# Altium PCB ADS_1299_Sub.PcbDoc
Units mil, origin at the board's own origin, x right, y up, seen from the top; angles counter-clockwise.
Board outline 2450.29 x 2305.45 mil, 4 copper layers (Top Layer, GND, DVDD, Bottom Layer), stack 23.756 mil thick; 58 components, 57 nets, 236 pads, 60 vias.
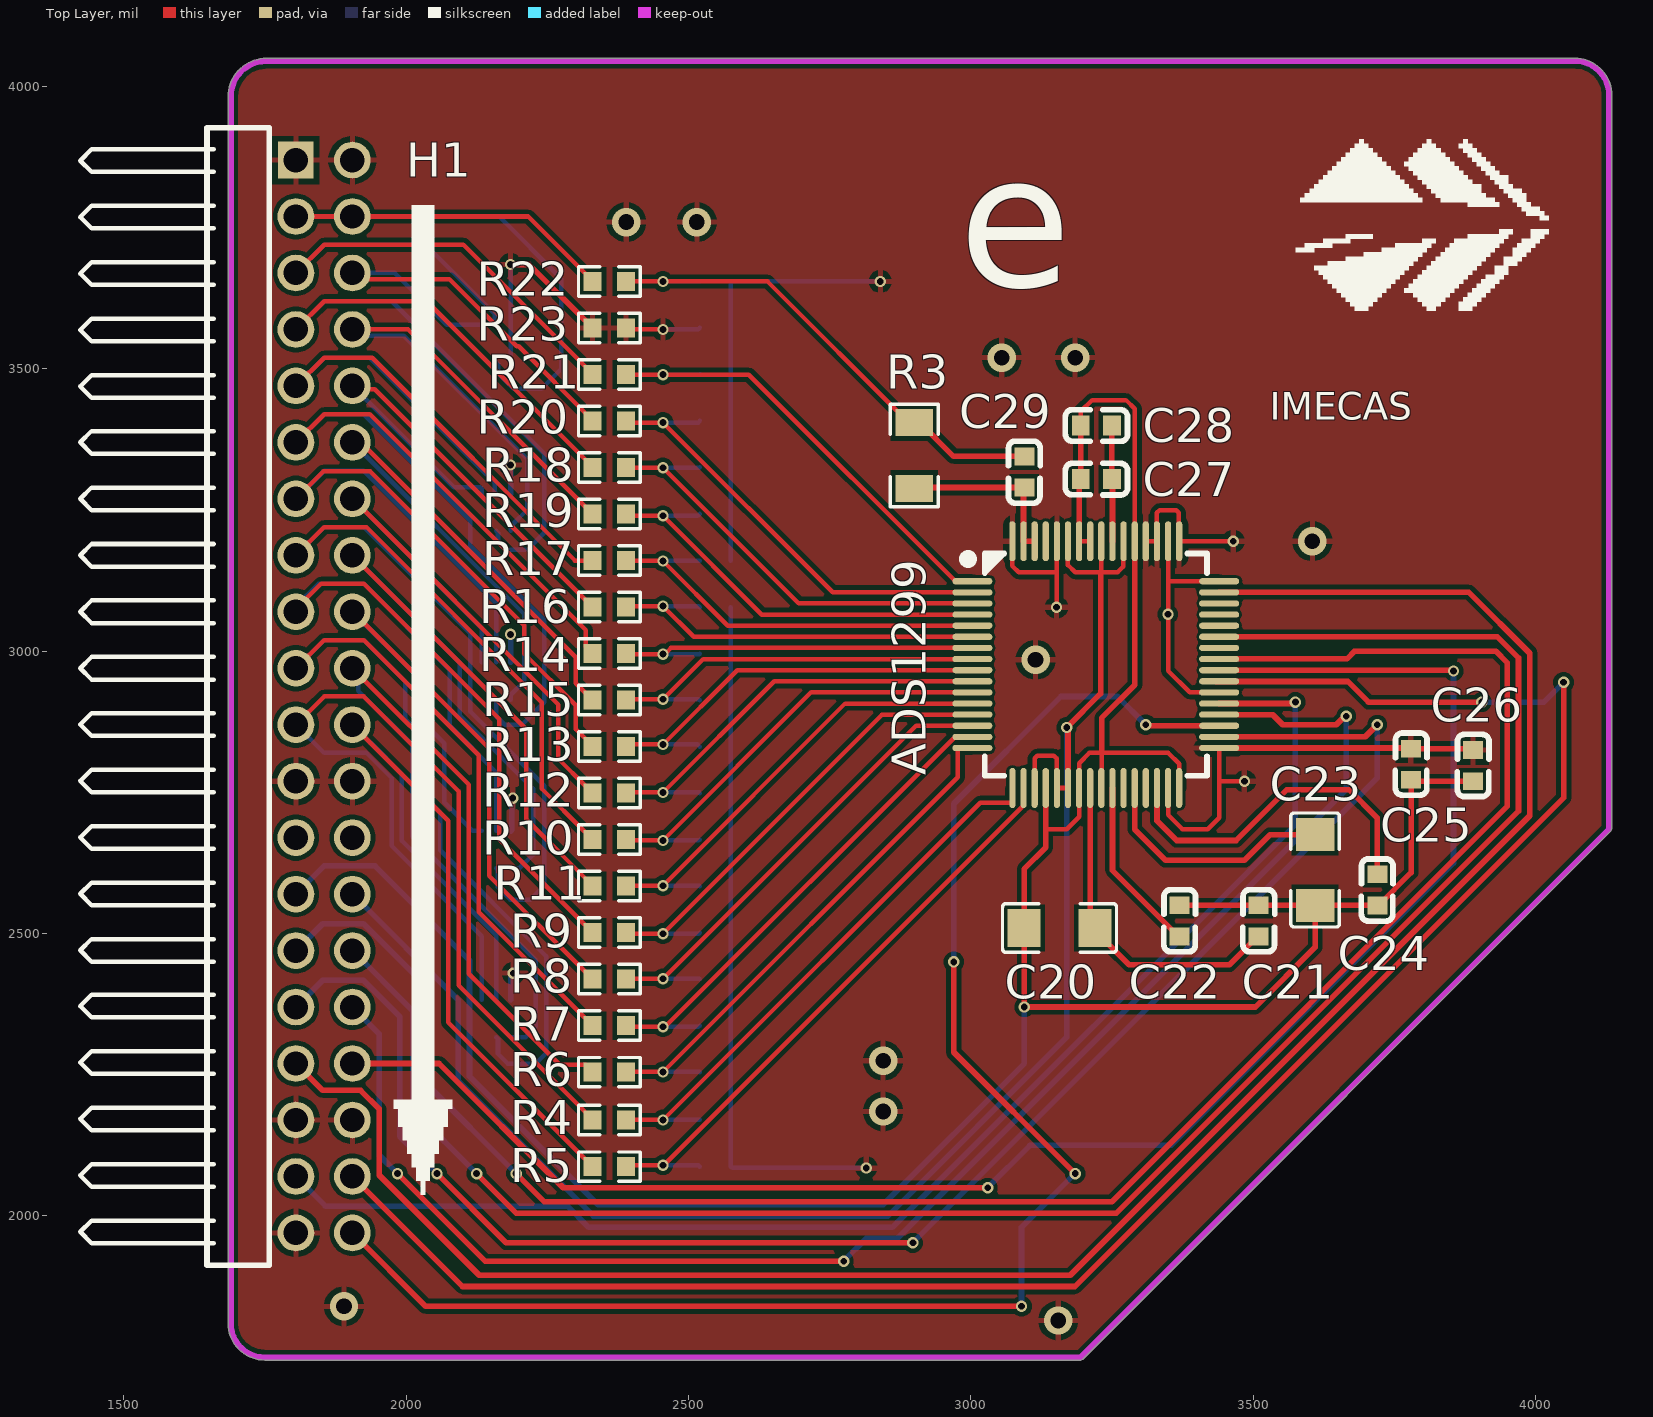
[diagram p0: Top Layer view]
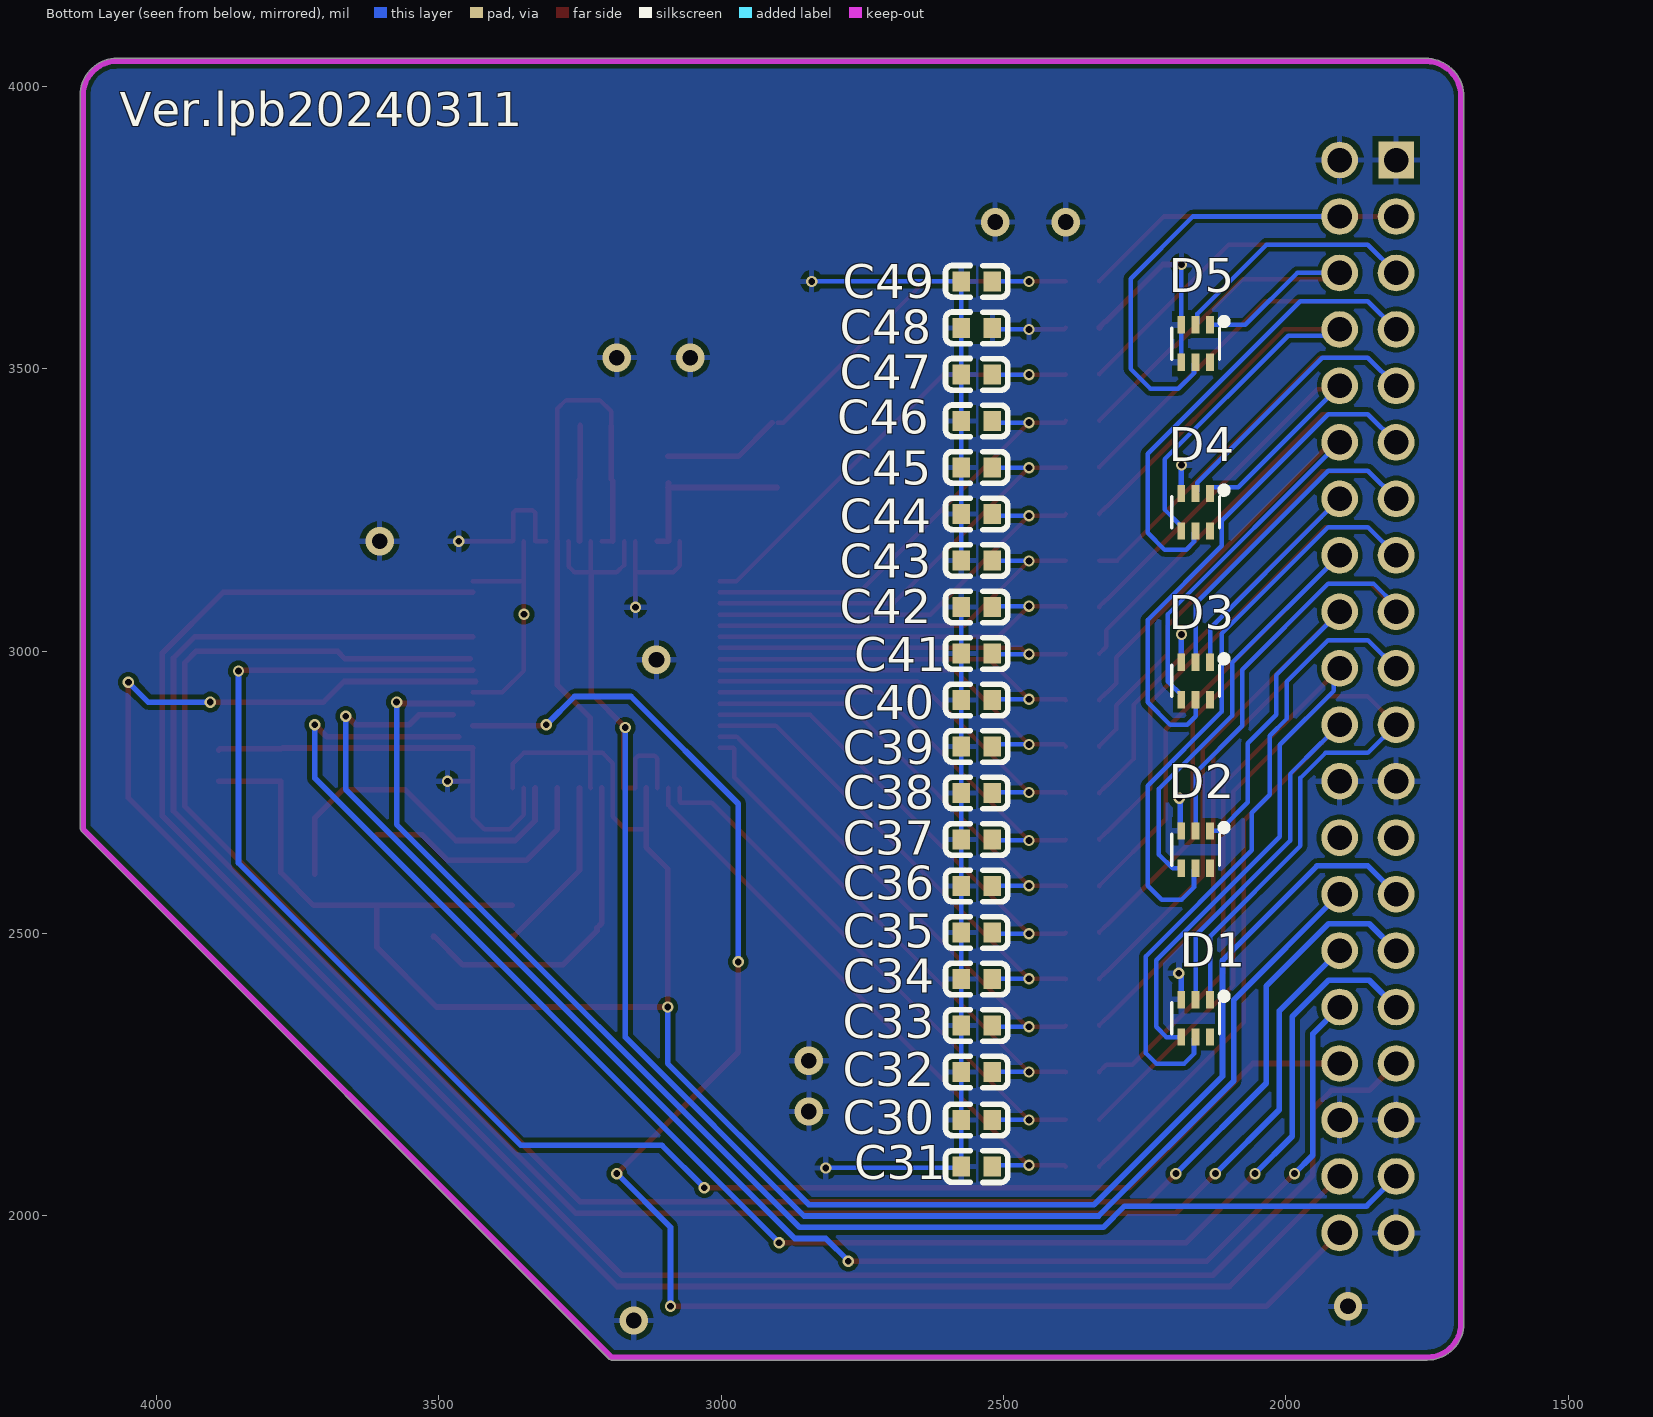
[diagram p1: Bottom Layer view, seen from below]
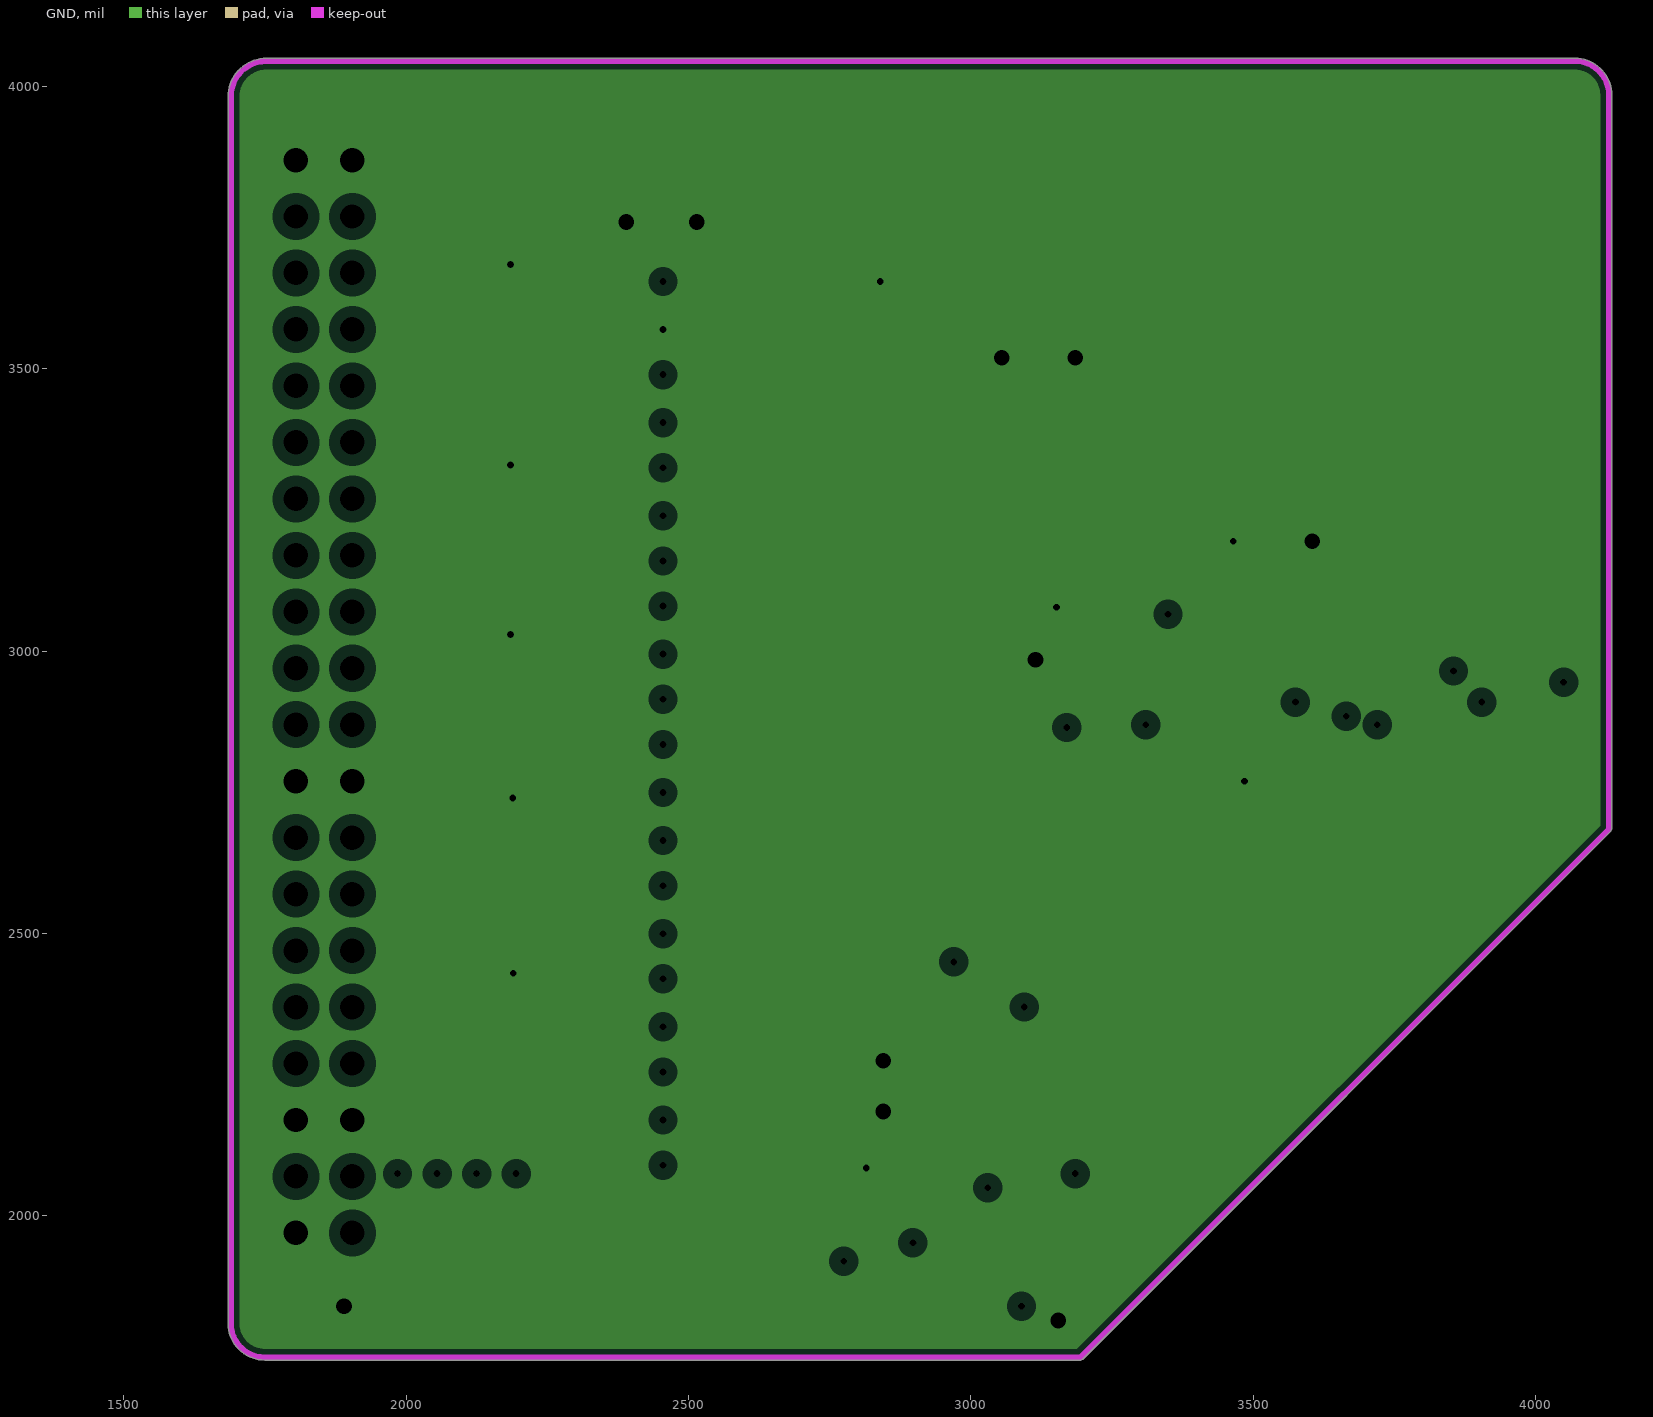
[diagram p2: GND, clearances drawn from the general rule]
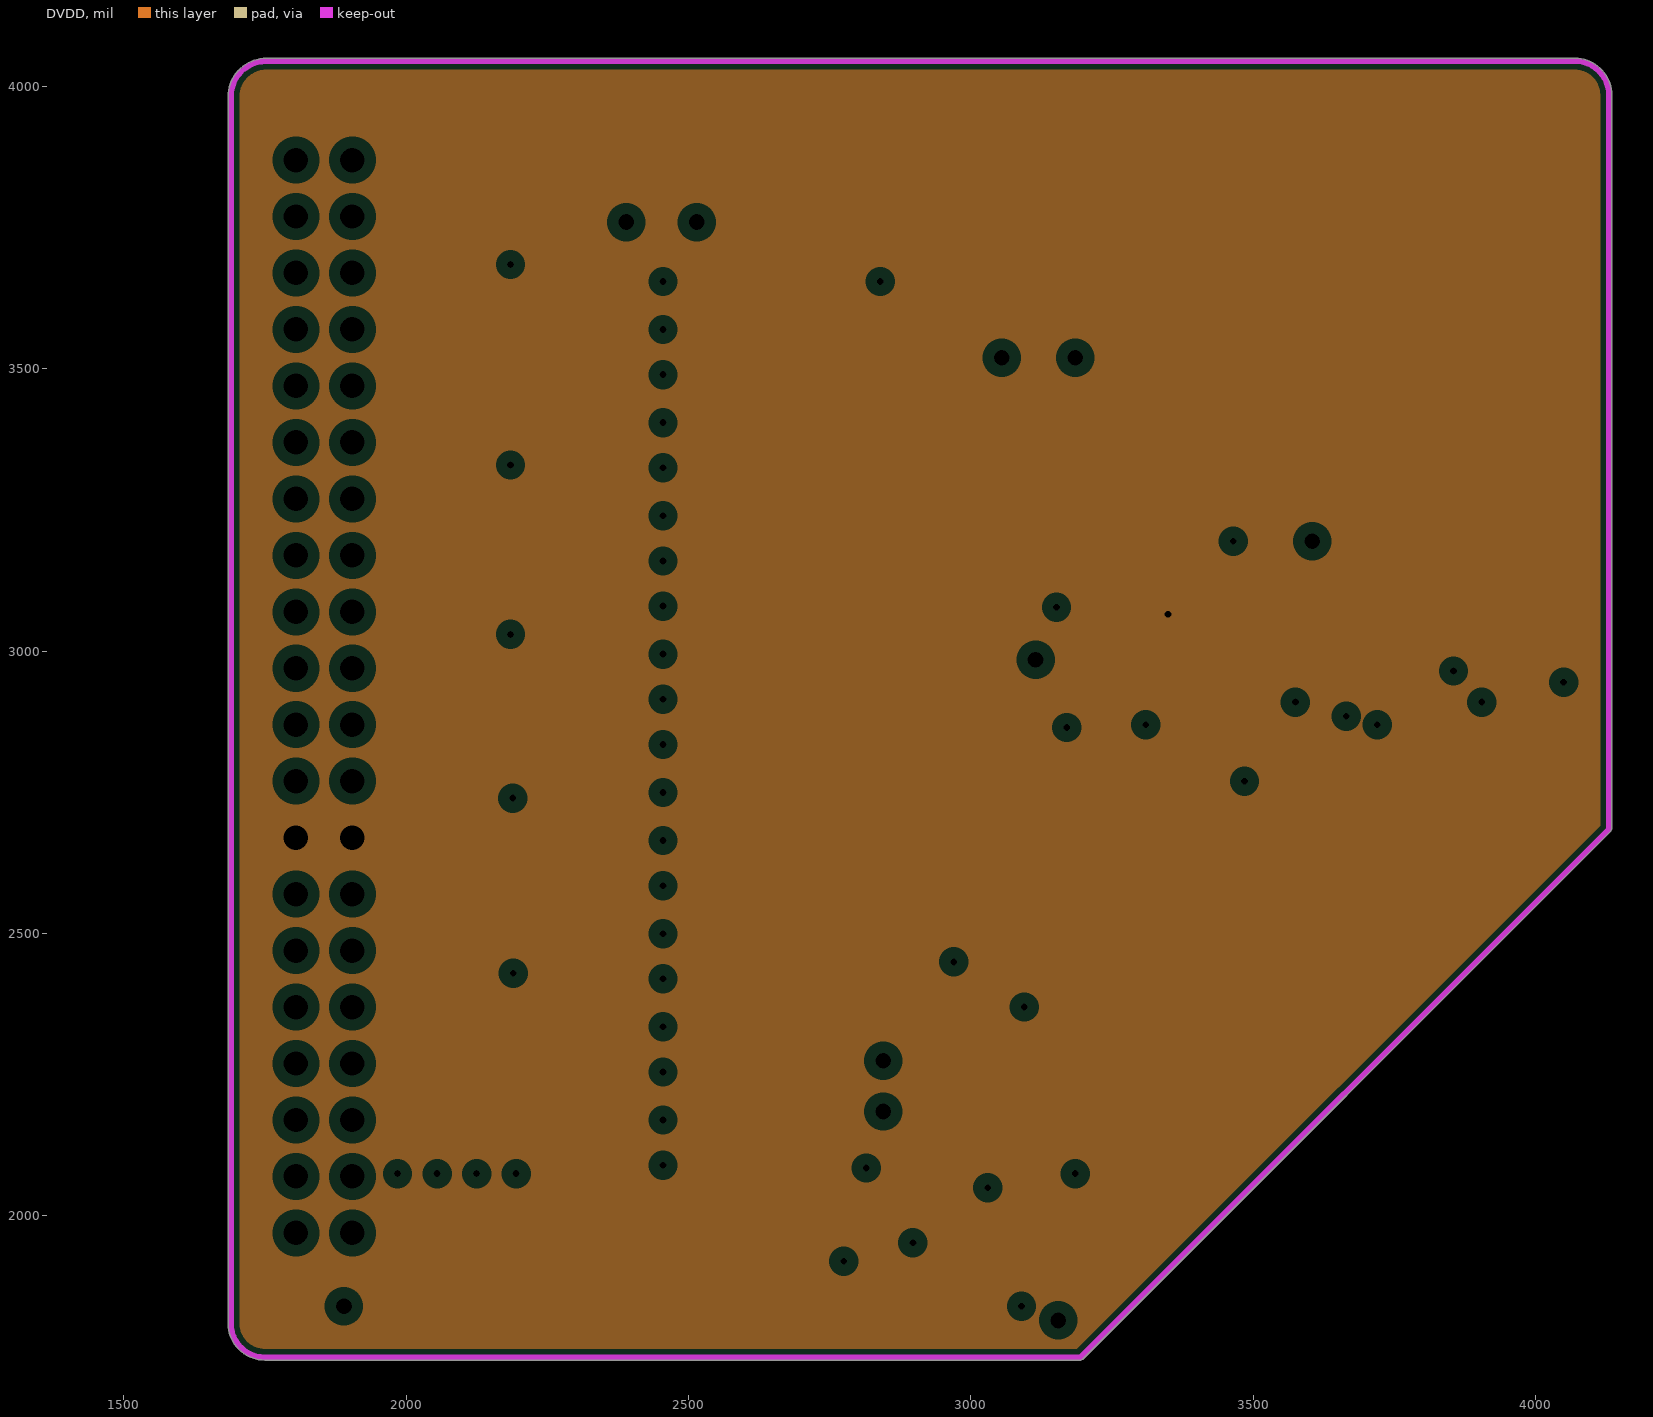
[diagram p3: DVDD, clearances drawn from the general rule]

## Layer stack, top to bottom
Top Solder: solder mask 0.4, Solder Resist, Dk 3.5
Top Layer: signal copper 1.4
Dielectric 2: prepreg 2.8, PP-006, Dk 4.1
GND: plane copper 1.378, net GND
Dielectric 1: dielectric 12.6, FR-4, Dk 4.8
DVDD: plane copper 1.378, net DVDD
Dielectric 3: prepreg 2.8, PP-006, Dk 4.1
Bottom Layer: signal copper 1.4
Bottom Solder: solder mask 0.4, Solder Resist, Dk 3.5

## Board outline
1685.07,1803.77 ccw(c1750,1810) 1750,1744.78 3194.79,1744.78 3198.34,1746.25 4133.75,2681.66 4135.22,2685.21 4135.22,3985 ccw(c4070,3985) 4070,4050.22 4068.76,4050.07 1752.5,4050.07 ccw(c1752.5,3982.5) 1684.93,3982.5

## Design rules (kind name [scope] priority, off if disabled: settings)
Clearance ads1299 [HasFootprint('TQFP-64_L10.0-W10.0-P0.50-LS12.0-TL')] p1: gap=5 ignorepadtopadclearanceinfootprint=FALSE
Clearance [All] p2: gap=8 ignorepadtopadclearanceinfootprint=FALSE
PlaneClearance [All] p1: clearance=20
PlaneConnect [All] p1: planeconnectstyle=Relief reliefexpansion=20 reliefentries=4 reliefconductorwidth=10 reliefairgap=10
PolygonConnect [All] p1: connectstyle=Relief reliefconductorwidth=10 reliefentries=4 polygonreliefangle="90 Angle" airgapwidth=10
RoutingVias [All] p1: holewidth=12 width=20 viastyle="Through Hole" minholewidth=12 minwidth=20 maxholewidth=28 maxwidth=50
SolderMaskExpansion [All] p1: expansion=4 istentingtop=FALSE
Width [All] p1: maxlimit=10 minlimit=5 preferedwidth=8 minimp=50.000000 maximp=50.000000 favimp=50.000000
28 further rules are at their usual default settings.

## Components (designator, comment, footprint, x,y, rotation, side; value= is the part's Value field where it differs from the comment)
ADS1299 "ADS1299IPAGR" TQFP-64_L10.0-W10.0-P0.50-LS12.0-TL 3221.5,2976.42 r0 top (schematic designator U5)
C20 "CL31A106KBHNNNE" C1206 3157.3,2510 r0 top value=10uF
C21 "CC0603KRX7R9BB104" C0603 3510,2522.56 r270 top value=100nF
C22 "CL10A105KB8NNNC" C0603 3370,2522.56 r270 top value=1uF
C23 "CL31A107MQHNNNE" C1206 3610,2612.7 r90 top value=100uF
C24 "CL10A105KB8NNNC" C0603 3720,2577.56 r90 top value=1uF
C25 "CL10A105KB8NNNC" C0603 3780,2800 r270 top value=1uF
C26 "CL10A105KB8NNNC" C0603 3889.76,2797.56 r270 top value=1uF
C27 "CL10A105KB8NNNC" C0603 3222.44,3305 r180 top value=1uF
C28 "CC0603KRX7R9BB104" C0603 3222.44,3400 r180 top value=100nF
C29 "CL10B102KB8NNNC" C0603 3095,3317.56 r90 top value=1nF
C30 "CL10B102KB8NNNC" C0603 2547.56,2170 r180 bottom value=1nF
C31 "CL10B102KB8NNNC" C0603 2547.56,2087.37 r180 bottom value=1nF
C32 "CL10B102KB8NNNC" C0603 2547.56,2254.74 r180 bottom value=1nF
C33 "CL10B102KB8NNNC" C0603 2547.56,2337.11 r180 bottom value=1nF
C34 "CL10B102KB8NNNC" C0603 2547.56,2419.47 r180 bottom value=1nF
C35 "CL10B102KB8NNNC" C0603 2547.56,2501.84 r180 bottom value=1nF
C36 "CL10B102KB8NNNC" C0603 2547.56,2584.21 r180 bottom value=1nF
C37 "CL10B102KB8NNNC" C0603 2547.56,2666.58 r180 bottom value=1nF
C38 "CL10B102KB8NNNC" C0603 2547.56,2748.95 r180 bottom value=1nF
C39 "CL10B102KB8NNNC" C0603 2547.56,2831.32 r180 bottom value=1nF
C40 "CL10B102KB8NNNC" C0603 2547.56,2913.68 r180 bottom value=1nF
C41 "CL10B102KB8NNNC" C0603 2547.56,2996.05 r180 bottom value=1nF
C42 "CL10B102KB8NNNC" C0603 2547.56,3078.42 r180 bottom value=1nF
C43 "CL10B102KB8NNNC" C0603 2547.56,3160.79 r180 bottom value=1nF
C44 "CL10B102KB8NNNC" C0603 2547.56,3243.16 r180 bottom value=1nF
C45 "CL10B102KB8NNNC" C0603 2547.56,3325.53 r180 bottom value=1nF
C46 "CL10B102KB8NNNC" C0603 2547.56,3407.89 r180 bottom value=1nF
C47 "CL10B102KB8NNNC" C0603 2547.56,3490.26 r180 bottom value=1nF
C48 "CL10B102KB8NNNC" C0603 2547.56,3572.63 r180 bottom value=1nF
C49 "CL10B102KB8NNNC" C0603 2547.56,3655 r180 bottom value=1nF
D1 "TPD4E1B06DCKR" SC-70-6_L2.2-W1.3-P0.65-LS2.1-BL 2160,2350 r0 bottom
D2 "TPD4E1B06DCKR" SC-70-6_L2.2-W1.3-P0.65-LS2.1-BL 2160,2648.75 r0 bottom
D3 "TPD4E1B06DCKR" SC-70-6_L2.2-W1.3-P0.65-LS2.1-BL 2160,2947.5 r0 bottom
D4 "TPD4E1B06DCKR" SC-70-6_L2.2-W1.3-P0.65-LS2.1-BL 2160,3246.25 r0 bottom
D5 "TPD4E1B06DCKR" SC-70-6_L2.2-W1.3-P0.65-LS2.1-BL 2160,3545 r0 bottom
H1 "PZ254-2-20-W-8.5_C2895000" HDR-TH_40P-P2.54-H-M-R2-C20-S2.54 1855,2920 r270 top
R3 "1206W4F1004T5E" R1206 2900,3346.78 r90 top value=1MΩ
R4 "0603WAF2201T5E" R0603 2360,2170 r180 top value=2.2kΩ
R5 "0603WAF2201T5E" R0603 2360,2087.37 r180 top value=2.2kΩ
R6 "0603WAF2201T5E" R0603 2360,2254.74 r180 top value=2.2kΩ
R7 "0603WAF2201T5E" R0603 2360,2337.11 r180 top value=2.2kΩ
R8 "0603WAF2201T5E" R0603 2360,2419.47 r180 top value=2.2kΩ
R9 "0603WAF2201T5E" R0603 2360,2501.84 r180 top value=2.2kΩ
R10 "0603WAF2201T5E" R0603 2360,2666.58 r180 top value=2.2kΩ
R11 "0603WAF2201T5E" R0603 2360,2584.21 r180 top value=2.2kΩ
R12 "0603WAF2201T5E" R0603 2360,2748.95 r180 top value=2.2kΩ
R13 "0603WAF2201T5E" R0603 2360,2831.32 r180 top value=2.2kΩ
R14 "0603WAF2201T5E" R0603 2360,2996.05 r180 top value=2.2kΩ
R15 "0603WAF2201T5E" R0603 2360,2913.68 r180 top value=2.2kΩ
R16 "0603WAF2201T5E" R0603 2360,3078.42 r180 top value=2.2kΩ
R17 "0603WAF2201T5E" R0603 2360,3160.79 r180 top value=2.2kΩ
R18 "0603WAF2201T5E" R0603 2360,3325.53 r180 top value=2.2kΩ
R19 "0603WAF2201T5E" R0603 2360,3243.16 r180 top value=2.2kΩ
R20 "0603WAF2201T5E" R0603 2360,3407.89 r180 top value=2.2kΩ
R21 "0603WAF2201T5E" R0603 2360,3490.26 r180 top value=2.2kΩ
R22 "0603WAF2201T5E" R0603 2360,3655 r180 top value=2.2kΩ
R23 "0603WAF2201T5E" R0603 2360,3572.63 r0 top value=2.2kΩ

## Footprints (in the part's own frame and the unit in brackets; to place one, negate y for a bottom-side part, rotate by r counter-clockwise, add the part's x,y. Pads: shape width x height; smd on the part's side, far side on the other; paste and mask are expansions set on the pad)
C0603 [mm]
  rect 0.8x0.9 smd: 1(-0.7,0) 2(0.7,0)
  silkscreen extent -1.41,-0.71 1.39,0.72
C1206 [mm]
  rect 1.485x1.728 smd paste-100 mask+0.051: 1(-1.593,0) 2(1.593,0)
  silkscreen extent -2.56,-1.09 2.56,1.09
HDR-TH_40P-P2.54-H-M-R2-C20-S2.54 [mm]
  rect 1.65x1.6 hole 1.1: 1(-24.13,-1.27)
  round 1.65 hole 1.1: 2(-24.13,1.27) 3(-21.59,-1.27) 4(-21.59,1.27) 5(-19.05,-1.27) 6(-19.05,1.27) 7(-16.51,-1.27) 8(-16.51,1.27) 9(-13.97,-1.27) 10(-13.97,1.27) 11(-11.43,-1.27) 12(-11.43,1.27) 13(-8.89,-1.27) 14(-8.89,1.27) 15(-6.35,-1.27) 16(-6.35,1.27) 17(-3.81,-1.27) 18(-3.81,1.27) 19(-1.27,-1.27) 20(-1.27,1.27) 21(1.27,-1.27) 22(1.27,1.27) 23(3.81,-1.27) 24(3.81,1.27) 25(6.35,-1.27) 26(6.35,1.27) 27(8.89,-1.27) 28(8.89,1.27) 29(11.43,-1.27) 30(11.43,1.27) 31(13.97,-1.27) 32(13.97,1.27) 33(16.51,-1.27) 34(16.51,1.27) 35(19.05,-1.27) 36(19.05,1.27) 37(21.59,-1.27) 38(21.59,1.27) 39(24.13,-1.27) 40(24.13,1.27)
  silkscreen extent -25.59,-10.97 25.59,-2.47
R0603 [mil]
  rect 31.75x34.02 smd paste-3937.01 mask+2: 1(-29.66,0) 2(29.66,0)
  silkscreen extent -55,-26 55,26
R1206 [mil]
  rect 47.54x66.97 smd paste-3937.01 mask+2: 1(-58.22,0) 2(58.22,0)
  silkscreen extent -91,-42 91,42
SC-70-6_L2.2-W1.3-P0.65-LS2.1-BL [mm]
  rect 0.35x0.78 smd: 1(-0.65,-0.84) 2(0,-0.84) 3(0.65,-0.84) 4(0.65,0.84) 5(0,0.84) 6(-0.65,0.84)
  silkscreen extent -1.43,-1.14 1.08,0.7
TQFP-64_L10.0-W10.0-P0.50-LS12.0-TL [mm]
  oval 1.8x0.28 smd paste-100 mask+0.051: 1(-5.55,3.75) 2(-5.55,3.25) 3(-5.55,2.75) 4(-5.55,2.25) 5(-5.55,1.75) 6(-5.55,1.25) 7(-5.55,0.75) 8(-5.55,0.25) 9(-5.55,-0.25) 10(-5.55,-0.75) 11(-5.55,-1.25) 12(-5.55,-1.75) 13(-5.55,-2.25) 14(-5.55,-2.75) 15(-5.55,-3.25) 16(-5.55,-3.75) 33(5.55,-3.75) 34(5.55,-3.25) 35(5.55,-2.75) 36(5.55,-2.25) 37(5.55,-1.75) 38(5.55,-1.25) 39(5.55,-0.75) 40(5.55,-0.25) 41(5.55,0.25) 42(5.55,0.75) 43(5.55,1.25) 44(5.55,1.75) 45(5.55,2.25) 46(5.55,2.75) 47(5.55,3.25) 48(5.55,3.75)
  oval 0.28x1.8 smd paste-100 mask+0.051: 17(-3.75,-5.55) 18(-3.25,-5.55) 19(-2.75,-5.55) 20(-2.25,-5.55) 21(-1.75,-5.55) 22(-1.25,-5.55) 23(-0.75,-5.55) 24(-0.25,-5.55) 25(0.25,-5.55) 26(0.75,-5.55) 27(1.25,-5.55) 28(1.75,-5.55) 29(2.25,-5.55) 30(2.75,-5.55) 31(3.25,-5.55) 32(3.75,-5.55) 49(3.75,5.55) 50(3.25,5.55) 51(2.75,5.55) 52(2.25,5.55) 53(1.75,5.55) 54(1.25,5.55) 55(0.75,5.55) 56(0.25,5.55) 57(-0.25,5.55) 58(-0.75,5.55) 59(-1.25,5.55) 60(-1.75,5.55) 61(-2.25,5.55) 62(-2.75,5.55) 63(-3.25,5.55) 64(-3.75,5.55)
  silkscreen extent -5.95,-5 5,5

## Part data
ADS1299: "ADS1299", JLCPCB Part Class="Extended Part", Manufacturer=TI(德州仪器), Supply Voltage=5V；1.8V~3.6V
C20: "10uf电容", JLCPCB Part Class="Basic Part", LCSC Part Name="10uF ±10% 50V", Manufacturer=SAMSUNG(三星), Temperature Coefficient=X5R, Tolerance=±10%, Voltage Rated=50V
C21 C28: "0.1uf电容", JLCPCB Part Class="Basic Part", LCSC Part Name="100nF ±10% 50V", Manufacturer=YAGEO(国巨), Temperature Coefficient=X7R, Tolerance=±10%, Voltage Rated=50V
C22 C24 C25 C26 C27: "1uf电容", JLCPCB Part Class="Basic Part", LCSC Part Name="1uF ±10% 50V", Manufacturer=SAMSUNG(三星), Temperature Coefficient=X5R, Tolerance=±10%, Voltage Rated=50V
C23: "100uf电容", JLCPCB Part Class="Basic Part", LCSC Part Name="100uF ±20% 6.3V", Manufacturer=SAMSUNG(三星), Temperature Coefficient=X5R, Tolerance=±20%, Voltage Rated=6.3V
C29 C30 C31 C32 C33 C34 C35 C36 C37 C38 C39 C40 C41 C42 C43 C44 C45 C46 C47 C48 C49: "1nf电容", JLCPCB Part Class="Basic Part", LCSC Part Name="1nF ±10% 50V", Manufacturer=SAMSUNG(三星), Temperature Coefficient=X7R, Tolerance=±10%, Voltage Rated=50V
D1 D2 D3 D4 D5: "TPD4", JLCPCB Part Class="Extended Part", Manufacturer=TI(德州仪器)
H1: "2*20P", Color=黑色, Current Rating (Max)=3A, JLCPCB Part Class="Extended Part", LCSC Part Name="2.54mm 2x20P 弯插 方针", Manufacturer=HCTL(华灿天禄), Manufacturer Part=PZ254-2-20-W-8.5, Operating Temperature Range=-40℃~+105℃, Voltage Rating (Max)=-
R3: "1M电阻", JLCPCB Part Class="Basic Part", LCSC Part Name="1MΩ ±1% 250mW 厚膜电阻", Manufacturer=UNI-ROYAL(厚声), Operating Temperature Range=-55℃~+155℃, Overload Voltage (Max)=200V, Power(Watts)=250mW, Temperature Coefficient=±100ppm/℃, Tolerance=±1%
R4 R5 R6 R7 R8 R9 R10 R11 R12 R13 R14 R15 R16 R17 R18 R19 R20 R21 R22 R23: "2.2k电阻", JLCPCB Part Class="Basic Part", LCSC Part Name="2.2kΩ ±1% 100mW 厚膜电阻", Manufacturer=UNI-ROYAL(厚声), Operating Temperature Range=-55℃~+155℃, Overload Voltage (Max)=75V, Power(Watts)=100mW, Temperature Coefficient=±100ppm/℃, Tolerance=±1%

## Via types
v1: diameter 20, hole 12, Top Layer to Bottom Layer, 50 vias
v2: diameter 50, hole 28, Top Layer to Bottom Layer, 10 vias

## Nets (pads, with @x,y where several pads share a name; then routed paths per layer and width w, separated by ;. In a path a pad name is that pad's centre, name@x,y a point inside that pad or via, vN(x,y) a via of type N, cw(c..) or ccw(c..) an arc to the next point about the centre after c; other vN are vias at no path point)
AVDD: ADS1299.19 ADS1299.21 ADS1299.22 ADS1299.54 ADS1299.56 ADS1299.59 H1.28 | length 3089.8
  Top Layer w8: ADS1299.19 3113.23,2810.31 3117.92,2815 3147.34,2815 3152.02,2810.31 3152.02,2758.5 ADS1299.21 ADS1299.22 ; ADS1299.59 3172.29,3152.71 3185,3140 3230,3140 ; ADS1299.56 3231.34,3141.34 3230,3140 ; ADS1299.54 3270.13,3194.34 3270.13,3150.13 3260,3140 3230,3140
  Top Layer w10: ADS1299.22 3172.29,2860 3170,2862.29 v1(3170,2865) 3230,2925 3230,3140
  Bottom Layer w10: H1.28 2092.52,2382.48 2092.52,2239.2 2331.72,2000 2853.28,2000 3170,2316.72 v1(3170,2865)
AVSS: ADS1299.20 ADS1299.23 ADS1299.25 ADS1299.32 ADS1299.53 ADS1299.57 ADS1299.58 C20.1 C21.1 C22.1 C23.1 C24.1 C25.2 C26.2 C27.2 C28.2 H1.27 | length 5081.8
  Top Layer w8: 3132.92,2685 3170,2685 3191.97,2706.97 ADS1299.23 3191.97,2801.97 3210,2820 3231.92,2820 ; ADS1299.58 ADS1299.57 ; C27.2@3191.97,3302.09 C27.2 ; C28.2 3195.03,3400.15 3195.03,3425.03 3215,3445 3275,3445 3290.4,3429.6 ADS1299.53 ; ADS1299.25 3231.92,2758.5 3231.92,2820 ; ADS1299.32 3369.14,2800.86 3350,2820 3231.92,2820
  Top Layer w10: ADS1299.20 3132.92,2685 3132.92,2652.53 3094.6,2614.21 C20.1 3095,2509.6 v1(3095,2370) 3504.14,2370 3610,2475.86 C23.1 ; ADS1299.58 C27.2@3191.97,3302.09 ; C27.2 C28.2 ; 3231.92,2820 3231.92,2881.92 3290.4,2940.4 ADS1299.53 ; C22.1 C21.1 3609.88,2550.12 C23.1 ; C26.2@3890,2769.88 3889.88,2770 C26.2 3780,2770 3780,2608.03 3721.97,2550 C24.1 C23.1
  Bottom Layer w10: H1.27 1855,2620 1945,2620 2112.52,2452.48 2112.52,2247.48 2340,2020 2845,2020 3095,2270 v1(3095,2370)
DVDD: ADS1299.38 ADS1299.48 ADS1299.50 H1.25 H1.26 | length 426.4
  Top Layer w8: ADS1299.50 3349.45,3124.06 ; ADS1299.38 3387.79,2927.21 3349.45,2965.55 v1(3349.45,3065.55) 3349.45,3124.06 ; ADS1299.48 3349.45,3124.06
GND: ADS1299.31 ADS1299.33 ADS1299.49 ADS1299.51 ADS1299.52 ADS1299.60 ADS1299.64 C25.1 C26.1 C30.1 C31.1 C32.1 C33.1 C34.1 C35.1 C36.1 C37.1 C38.1 C39.1 C40.1 C41.1 C42.1 C43.1 C44.1 C45.1 C46.1 C47.1 C48.1 C48.2 C49.1 D1.3 D2.3 D3.3 D4.3 D5.3 D5.4 H1.1 H1.2 H1.23 H1.24 H1.35 H1.36 H1.39 R23.1 R23.2 | length 3980.5
  Top Layer w8: R23.2 2392.29,3570 v1(2455,3570) ; ADS1299.64 3073.86,3151.14 3085,3140 3150,3140 3152.02,3142.02 ; v1(3152.02,3077.98) 3152.02,3142.02 ; ADS1299.60 3152.02,3194.34 3152.02,3142.02 ; ADS1299.52 ADS1299.51 3329.77,3245.31 3334.46,3250 3363.88,3250 3368.56,3245.31 3368.56,3195.5 ADS1299.49 3369.22,3195 v1(3465,3195) ; ADS1299.31 3349.45,2710.55 3375,2685 3420,2685 3440,2705 3440,2766.89 ; ADS1299.33 3440,2766.89 ; v1(3485,2770) 3443.11,2770 3440,2766.89
  Top Layer w10: v1(2185,3685) 2217.97,3685 2318.33,3584.64 2319.46,3584.64 2330.34,3573.76 R23.1 ; ADS1299.33 C25.1@3776.34,2828.78 ; C25.1 3887.32,2827.56 C26.1 3889.88,2825 C26.1@3890,2825
  Bottom Layer w8: D4.3@2182.7,3276.43 D4.3 ; v1(2185,3685) 2185.3,3684.7 2185.3,3578.36 D5.3 D5.4 ; v1(2455,3570) 2517.37,3570 C48.2 ; C42.1 C41.1 C40.1 C39.1 C38.1 C37.1 C36.1 C35.1 C34.1 C33.1 C32.1 C30.1 C31.1 2577.49,2085 v1(2815,2085) ; C43.1 C44.1 C45.1 C46.1 C47.1 C48.1 C49.1 v1(2840,3655)
  Bottom Layer w10: v1(2185,3030) 2185.3,3029.7 2185.3,2980.86 D3.3 ; v1(2185,3330) 2185.3,3329.7 2185.3,3279.61 D4.3 ; D1.3 2185.59,2422.88 2190,2427.29 v1(2190,2430) ; D2.3 2187.3,2683.53 2187.3,2738.3 v1(2189,2740)
  other v2: 3155,1815 1890,1840 2845,2185 2845,2275 3115,2985 3605,3195 3055,3520 3185,3520 2390,3760 2515,3760
NetC20_2: ADS1299.24 C20.2 C21.2 | length 591.8
  Top Layer w10: ADS1299.24 3211.66,2518.34 C20.2 3220,2505.22 3280.22,2445 3458.03,2445 3508.03,2495 C21.2
NetC22_2: ADS1299.26 C22.2 | length 313.4
  Top Layer w10: ADS1299.26 3251.03,2612 3368.03,2495 C22.2
NetC23_2: ADS1299.28 C23.2 | length 434.3
  Top Layer w10: ADS1299.28 3290.6,2757.72 3290.6,2684.4 3345,2630 3485,2630 3530.4,2675.4 C23.2
NetC24_2: ADS1299.30 C24.2 | length 620.4
  Top Layer w10: ADS1299.30 3329.97,2757.72 3329.97,2700.03 3365,2665 3470,2665 3560,2755 3670,2755 3720,2705 C24.2
NetC27_1: ADS1299.55 C27.1 C28.1 | length 205.5
  Top Layer w8: C27.1 C27.1@3251.03,3303.97
  Top Layer w10: C27.1 C28.1 ; ADS1299.55 C27.1@3251.03,3303.97
NetC29_1: ADS1299.62 ADS1299.63 C29.1 R3.1 | length 318.9
  Top Layer w10: R3.1@2901.44,3290 C29.1 C29.1@3093.55,3288.55 ; C29.1@3093.55,3298.55 ADS1299.63 ADS1299.62
NetC29_2: C29.2 C49.2 R3.2 R22.1 | length 889
  Top Layer w8: R22.1 v1(2455,3655) 2640.29,3655 2890.29,3405 R3.2
  Top Layer w10: R3.2@2909.71,3405 2969.59,3345.12 C29.2
  Bottom Layer w8: v1(2455,3655) C49.2
NetC30_2: ADS1299.17 C30.2 R4.1 | length 1007.1
  Top Layer w8: R4.1 v1(2455,2170) 3017,2732 3072.46,2732 3073.86,2733.4 ADS1299.17
  Bottom Layer w8: v1(2455,2170) C30.2
NetC31_2: ADS1299.18 C31.2 R5.1 | length 1065.7
  Top Layer w8: R5.1 2392.29,2090 v1(2455,2090) 2456.38,2090 3088.37,2721.99 3093.55,2727.18 ADS1299.18
  Bottom Layer w8: v1(2455,2090) 2517.37,2090 C31.2
NetC32_2: ADS1299.16 C32.2 R6.1 | length 945.7
  Top Layer w8: R6.1 2389.92,2255 v1(2455,2255) 2977.08,2777.08 2977.08,2827.38 2978.48,2828.78 ADS1299.16
  Bottom Layer w8: v1(2455,2255) 2519.74,2255 C32.2
NetC33_2: ADS1299.15 C33.2 R7.1 | length 892.8
  Top Layer w8: R7.1 2391.77,2335 v1(2455,2335) 2457.3,2337.3 2461.07,2337.3 2967.07,2843.29 ; 2967.08,2843.29 2972.26,2848.47 ADS1299.15
  Bottom Layer w8: v1(2455,2335) 2517.89,2335 C33.2
NetC34_2: ADS1299.14 C34.2 R8.1 | length 864.4
  Top Layer w8: R8.1 2390.19,2420 v1(2455,2420) 2903.15,2868.15 ADS1299.14
  Bottom Layer w8: v1(2455,2420) 2519.47,2420 C34.2
NetC35_2: ADS1299.13 C35.2 R9.1 | length 840.5
  Top Layer w8: R9.1 2391.5,2500 v1(2455,2500) 2842.84,2887.84 ADS1299.13
  Bottom Layer w8: v1(2455,2500) 2518.16,2500 C35.2
NetC36_2: ADS1299.12 C36.2 R11.1 | length 812.6
  Top Layer w8: R11.1 2390.45,2585 v1(2455,2585) 2777.52,2907.52 ADS1299.12
  Bottom Layer w8: v1(2455,2585) 2519.21,2585 C36.2
NetC37_2: ADS1299.11 C37.2 R10.1 | length 788.3
  Top Layer w8: R10.1 2391.24,2665 v1(2455,2665) 2717.21,2927.21 ADS1299.11
  Bottom Layer w8: v1(2455,2665) 2518.42,2665 C37.2
NetC38_2: ADS1299.10 C38.2 R12.1 | length 760.8
  Top Layer w8: R12.1 2390.71,2750 v1(2455,2750) 2651.89,2946.89 ADS1299.10
  Bottom Layer w8: v1(2455,2750) 2518.95,2750 C38.2
NetC39_2: ADS1299.9 C39.2 R13.1 | length 735.9
  Top Layer w8: R13.1 2393.34,2835 v1(2455,2835) 2586.58,2966.58 ADS1299.9
  Bottom Layer w8: v1(2455,2835) 2516.32,2835 C39.2
NetC40_2: ADS1299.8 C40.2 R15.1 | length 708.9
  Top Layer w8: R15.1 2390.98,2915 v1(2455,2915) 2526.26,2986.26 ADS1299.8
  Bottom Layer w8: v1(2455,2915) 2518.68,2915 C40.2
NetC41_2: ADS1299.7 C41.2 R14.1 | length 683.7
  Top Layer w8: R14.1 2390.71,2995 v1(2455,2995) 2458.25,2995 2469.2,3005.95 ADS1299.7
  Bottom Layer w8: v1(2455,2995) 2518.95,2995 C41.2
NetC42_2: ADS1299.6 C42.2 R16.1 | length 702.2
  Top Layer w8: R16.1 2391.24,3080 v1(2455,3080) 2509.37,3025.63 ADS1299.6
  Bottom Layer w8: v1(2455,3080) 2518.42,3080 C42.2
NetC43_2: ADS1299.5 C43.2 R17.1 | length 726.5
  Top Layer w8: R17.1 2390.45,3160 v1(2455,3160) 2569.68,3045.32 ADS1299.5
  Bottom Layer w8: v1(2455,3160) 2519.21,3160 C43.2
NetC44_2: ADS1299.4 C44.2 R19.1 | length 753.4
  Top Layer w8: R19.1 2392.82,3240 v1(2455,3240) 2630,3065 ADS1299.4
  Bottom Layer w8: v1(2455,3240) 2516.84,3240 C44.2
NetC45_2: ADS1299.3 C45.2 R18.1 | length 778.3
  Top Layer w8: R18.1 2390.19,3325 v1(2455,3325) 2695.31,3084.69 ADS1299.3
  Bottom Layer w8: v1(2455,3325) 2519.47,3325 C45.2
NetC46_2: ADS1299.2 C46.2 R20.1 | length 805.3
  Top Layer w8: R20.1 2392.55,3405 v1(2455,3405) 2755.63,3104.37 ADS1299.2
  Bottom Layer w8: v1(2455,3405) 2517.11,3405 C46.2
NetC47_2: ADS1299.1 C47.2 R21.1 | length 830.1
  Top Layer w8: R21.1 2389.92,3490 v1(2455,3490) 2607.14,3490 2973.08,3124.06 ADS1299.1
  Bottom Layer w8: v1(2455,3490) 2519.74,3490 C47.2
NetD1_1: D1.1 H1.21 R4.2 | length 1725.9
  Top Layer w8: H1.21 1855,2920 1925,2920 2093,2752 2093,2408.47 2330.34,2171.13 R4.2
  Bottom Layer w8: H1.21 1855,2820 1930,2820 1974.31,2775.69 1974.31,2655.69 2134.41,2495.59 D1.1
NetD1_2: D1.2 H1.22 R5.2 | length 1552.3
  Top Layer w8: H1.22 2075,2700 2075,2342.71 2317.33,2100.38 2318.46,2100.38 2330.34,2088.5 R5.2
  Bottom Layer w8: H1.22 1937,2838 1937.46,2838 1992.77,2782.68 1992.77,2664.36 2160,2497.14 D1.2
NetD1_4: D1.4 H1.20 R6.2 | length 1740
  Top Layer w8: H1.20 2111,2764 2111,2429 2272.26,2267.74 2318.46,2267.74 2330.34,2255.87 R6.2
  Bottom Layer w8: H1.20 1915.21,2959.79 1915.21,2929.79 2010.77,2834.23 2010.77,2671.82 2230,2452.59 2230,2335 2211.93,2316.93 D1.4
NetD1_5: D1.5 H1.19 R7.2 | length 2129.3
  Top Layer w8: H1.19 1855,3020 1925,3020 2129,2816 2129,2538.45 2317.33,2350.11 2318.46,2350.11 2330.34,2338.24 R7.2
  Bottom Layer w8: H1.19 1855,3020 1925,3020 1999.04,2945.96 1999.04,2880.16 2028.77,2850.42 2028.77,2745.77 2060.37,2714.18 2060.37,2647.68 2248,2460.05 2248,2288 2230,2270 2180,2270 2162.89,2287.11 2162.89,2314.04 D1.5
NetD2_1: D2.1 H1.18 R8.2 | length 1320.4
  Top Layer w8: H1.18 1905.46,3070 2147,2828.46 2147,2602.81 2317.33,2432.48 2318.46,2432.48 2330.34,2420.61 R8.2
  Bottom Layer w8: H1.18 2017.04,2957.96 2017.04,2887.61 2067.61,2837.04 2067.61,2732.39 2118.18,2681.82 D2.1
NetD2_2: D2.2 H1.17 R9.2 | length 1612.4
  Top Layer w8: H1.17 1805,3075 1850,3120 1925,3120 2165,2880 2165,2667.18 2317.33,2514.85 2318.46,2514.85 2330.34,2502.97 R9.2
  Bottom Layer w8: H1.17 1805,3080 1845,3120 1925,3120 2077.52,2967.48 2077.52,2867.99 2160,2785.51 D2.2
NetD2_4: D2.4 H1.16 R11.2 | length 1474
  Top Layer w8: H1.16 2213,2862 2213,2702.68 2330.34,2585.34 R11.2
  Bottom Layer w8: H1.16 2095.52,2979.48 2095.52,2885.82 2225,2756.34 2225,2640 2200.68,2615.68 D2.4
NetD2_5: D2.5 H1.15 R10.2 | length 1910.3
  Top Layer w8: H1.15 1855,3220 1930,3220 2240,2910 2240,2756.92 2317.33,2679.59 2318.46,2679.59 2330.34,2667.71 R10.2
  Bottom Layer w8: H1.15 1855,3220 1925,3220 2113.52,3031.48 2113.52,2893.28 2245,2761.8 2245,2585 2220,2560 2185,2560 2162.89,2582.11 2162.89,2612.79 D2.5
NetD3_1: D3.1 H1.14 R12.2 | length 1082.8
  Top Layer w8: H1.14 1905.46,3270 2270,2905.46 2270,2809.29 2317.33,2761.96 2318.46,2761.96 2330.34,2750.08 R12.2
  Bottom Layer w8: H1.14 1937.69,3237.77 2134.41,3041.05 D3.1
NetD3_2: D3.2 H1.13 R13.2 | length 1379.3
  Top Layer w8: H1.13 1853.44,3318.44 1936.56,3318.44 2209,3046 2209,2996 2300.46,2904.54 2300.46,2862.32 2330.34,2832.45 R13.2
  Bottom Layer w8: H1.13 1855,3320 1925,3320 2160,3085 D3.2
NetD3_4: D3.4 H1.12 R15.2 | length 1233.1
  Top Layer w8: H1.12 1920,3370 2300.46,2989.54 2300.46,2943.56 2317.33,2926.69 2318.46,2926.69 2330.34,2914.82 R15.2
  Bottom Layer w8: H1.12 2209,3066 2209,2946.3 2185.59,2922.89 D3.4
NetD3_5: D3.5 H1.11 R14.2 | length 1659.7
  Top Layer w8: H1.11 1855,3420 1936.08,3420 2318.46,3037.61 2318.46,3007.93 R14.2
  Bottom Layer w8: H1.11 1855,3420 1925,3420 2113.52,3231.48 2113.52,3186.94 2245,3055.46 2245,2909.69 2205.31,2870 2175,2870 2160,2885 D3.5
NetD4_1: D4.1 H1.10 R16.2 | length 901.6
  Top Layer w8: H1.10 1911.03,3463.97 1944.79,3463.97 2317.33,3091.43 2318.46,3091.43 2330.34,3079.55 R16.2
  Bottom Layer w8: H1.10 2084.33,3290.67 2131.52,3290.67 2134.41,3287.78 D4.1
NetD4_2: D4.2 H1.9 R17.2 | length 1179.9
  Top Layer w8: H1.9 1855,3520 1940,3520 2299.21,3160.79 R17.2
  Bottom Layer w8: H1.9 1855,3520 1935.77,3520 2157.11,3298.66 2157.11,3282.21 D4.2
NetD4_4: D4.4 H1.8 R19.2 | length 1105.7
  Top Layer w8: H1.8 2003.5,3570 2317.33,3256.17 2318.46,3256.17 2330.34,3244.29 R19.2
  Bottom Layer w8: H1.8 1915.9,3559.1 1995.9,3559.1 2215,3340 2215,3251.05 2185.59,3221.64 D4.4
NetD4_5: D4.5 H1.7 R18.2 | length 1502
  Top Layer w8: H1.7 1855,3620 2037,3620 2330.34,3326.66 R18.2
  Bottom Layer w8: H1.7 1855,3620 1975,3620 2245,3350 2245,3210 2215,3180 2176.73,3180 2162.89,3193.84 2162.89,3210.29 D4.5
NetD5_1: D5.1 H1.6 R20.2 | length 802.1
  Top Layer w8: H1.6 1915.9,3659.1 2076.96,3659.1 2196.06,3540 2199.37,3540 2330.34,3409.03 R20.2
  Bottom Layer w8: H1.6 1980,3670 2071.93,3578.07 D5.1
NetD5_2: D5.2 H1.5 R21.2 | length 1086
  Top Layer w8: H1.5 1855,3720 2101.74,3720 2330.34,3491.4 R21.2
  Bottom Layer w8: H1.5 1855,3720 2034.52,3720 2157.11,3597.41 2157.11,3580.96 D5.2
NetD5_5: D5.5 H1.3 H1.4 R22.2 | length 1307.8
  Top Layer w8: H1.3 H1.4 2216.47,3770 2330.34,3656.13 R22.2
  Bottom Layer w8: H1.4 2165,3770 2275,3660 2275,3500 2240,3465 2190.48,3465 2162.89,3492.59 2162.89,3509.04 D5.5
NetH1_29: ADS1299.41 H1.29 | length 3533.1
  Top Layer w10: v1(2195,2075) 2245,2025 3249.68,2025 3950,2725.32 3950,2980 3930,3000 3679.52,3000 3666.1,2986.58 ADS1299.41@3445,2986.58
  Bottom Layer w10: H1.29 1852.48,2517.48 1924.67,2517.48 2035,2407.15 2035,2235 v1(2195,2075)
NetH1_30: ADS1299.43 H1.30 | length 3471.8
  Top Layer w10: v1(2125,2075) 2195,2005 3257.96,2005 3970,2717.04 3970,2988.28 3932.65,3025.63 ADS1299.43
  Bottom Layer w10: H1.30 2011.8,2363.2 2011.8,2188.2 v1(2125,2075)
NetH1_31: ADS1299.34 H1.31 | length 2951.2
  Top Layer w10: v1(2055,2075) 2177.6,1952.4 v1(2897.6,1952.4) ; ADS1299.34@3465,2848.78 3698.78,2848.78 v1(3720,2870)
  Bottom Layer w10: H1.31 1852.48,2417.48 1924.67,2417.48 1988.88,2353.27 1988.88,2141.12 v1(2055,2075) ; v1(2897.6,1952.4) 2897.6,1952.96 3720,2775.36 v1(3720,2870)
NetH1_32: ADS1299.36 H1.32 | length 2751.6
  Top Layer w10: v1(1985,2075) 2140,1920 v1(2775,1920) ; ADS1299.36@3475,2887.52 3535,2887.52 3552.52,2870 3647.29,2870 3662.29,2885 v1(3665,2885)
  Bottom Layer w10: H1.32 1952.48,2322.52 1952.48,2107.52 v1(1985,2075) ; v1(2775,1920) 2815,1960 2869.85,1960 3665,2755.15 v1(3665,2885)
NetH1_33: ADS1299.47 H1.33 | length 3628.7
  Top Layer w10: H1.33 1852.48,2222.52 1919.63,2222.52 1952.48,2189.67 1952.48,2072.16 2129.64,1895 3176.25,1895 3990,2708.75 3990,2996.57 3882.2,3104.37 ADS1299.47
NetH1_34: ADS1299.40 H1.34 | length 3035
  Top Layer w10: H1.34 2058.49,2270 2278.49,2050 v1(3030,2050) ; ADS1299.40 3853.42,2966.58 v1(3855,2965)
  Bottom Layer w10: v1(3030,2050) 3105,2125 3355,2125 3855,2625 v1(3855,2965)
NetH1_37: ADS1299.37 H1.37 | length 2455.4
  Top Layer w10: ADS1299.37 3569.81,2907.52 3572.29,2910 v1(3575,2910)
  Bottom Layer w10: H1.37 1857.52,2017.48 2285.95,2017.48 2323.43,1980 2861.57,1980 3575,2693.43 v1(3575,2910)
NetH1_38: ADS1299.39 H1.38 | length 3433.4
  Top Layer w10: H1.38 2100,1875 3184.53,1875 4050,2740.47 v1(4050,2945) ; ADS1299.39@3435,2946.58 3668,2946.58 3704.58,2910 v1(3905,2910)
  Bottom Layer w10: v1(3905,2910) 4015,2910 v1(4050,2945)
NetH1_40: ADS1299.35 H1.40 | length 2827.4
  Top Layer w10: H1.40 2035,1840 v1(3090,1840) ; v1(2970,2450) 2970,2290 v1(3185,2075) ; v1(3310,2870) 3311.85,2868.15 ADS1299.35
  Bottom Layer w10: v1(2970,2450) 2970,2730 3160,2920 3260,2920 v1(3310,2870) ; v1(3090,1840) 3090,1980 v1(3185,2075)
pads on no net: ADS1299.27 ADS1299.29 ADS1299.42 ADS1299.44 ADS1299.45 ADS1299.46 ADS1299.61 D1.6 D2.6 D3.6 D4.6 D5.6

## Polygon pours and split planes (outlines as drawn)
GND on Bottom Layer "GND_L04_P001" (solid, pour order 1): 1685.07,1803.77 ccw(c1750,1810) 1750,1744.78 3194.79,1744.78 3198.34,1746.25 4133.75,2681.66 4135.22,2685.21 4135.22,3985 ccw(c4070,3985) 4070,4050.22 4068.76,4050.07 1752.5,4050.07 ccw(c1752.5,3982.5) 1684.93,3982.5
GND on Top Layer "GND_L01_P000" (solid, pour order 0): 1685.07,1803.77 ccw(c1750,1810) 1750,1744.78 3194.79,1744.78 3198.34,1746.25 4133.75,2681.66 4135.22,2685.21 4135.22,3985 ccw(c4070,3985) 4070,4050.22 4068.76,4050.07 1752.5,4050.07 ccw(c1752.5,3982.5) 1684.93,3982.5
DVDD on DVDD (split plane): 4075.9,4029.83 4081.7,4028.68 4087.3,4026.78 4092.61,4024.16 4097.53,4020.88 4101.98,4016.98 4105.88,4012.53 4109.16,4007.61 4111.78,4002.3 4113.68,3996.7 4114.83,3990.9 4115.18,3985.57 4115.13,3985 4115.13,2691.46 3188.54,1764.87 1750,1764.87 1749.43,1764.82 1744.1,1765.17 1738.3,1766.32 1732.7,1768.22 1727.39,1770.84 1722.47,1774.12 1718.02,1778.02 1714.12,1782.47 1710.84,1787.39 1708.22,1792.7 1706.32,1798.3 1705.17,1804.08 1705.03,3982.5 1704.99,3982.97 1705.26,3987.83 1706.15,3993.08 1707.63,3998.2 1709.67,4003.13 1712.25,4007.8 1715.33,4012.14 1718.88,4016.12 1722.86,4019.67 1727.21,4022.76 1731.87,4025.33 1736.8,4027.38 1741.92,4028.85 1747.18,4029.74 1752.04,4030.02 1752.5,4029.97 4068.76,4029.97 4070.01,4030.09 4071.26,4030.13 4071.31,4030.13
GND on GND (split plane): 4075.9,4029.83 4081.7,4028.68 4087.3,4026.78 4092.61,4024.16 4097.53,4020.88 4101.98,4016.98 4105.88,4012.53 4109.16,4007.61 4111.78,4002.3 4113.68,3996.7 4114.83,3990.9 4115.18,3985.57 4115.13,3985 4115.13,2691.46 3188.54,1764.87 1750,1764.87 1749.43,1764.82 1744.1,1765.17 1738.3,1766.32 1732.7,1768.22 1727.39,1770.84 1722.47,1774.12 1718.02,1778.02 1714.12,1782.47 1710.84,1787.39 1708.22,1792.7 1706.32,1798.3 1705.17,1804.08 1705.03,3982.5 1704.99,3982.97 1705.26,3987.83 1706.15,3993.08 1707.63,3998.2 1709.67,4003.13 1712.25,4007.8 1715.33,4012.14 1718.88,4016.12 1722.86,4019.67 1727.21,4022.76 1731.87,4025.33 1736.8,4027.38 1741.92,4028.85 1747.18,4029.74 1752.04,4030.02 1752.5,4029.97 4068.76,4029.97 4070.01,4030.09 4071.26,4030.13 4071.31,4030.13

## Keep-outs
Keep-Out Layer:
  lines w10: 1689.79,1810 ccw(c1750,1810) 1750,1749.79 3194.79,1749.79 4130.21,2685.21 4130.21,3985 ccw(c4070,3985) 4070,4045.21 ; 1689.95,1804.95 1689.95,3982.5 cw(c1752.5,3982.5) 1752.5,4045.05 4069.84,4045.05

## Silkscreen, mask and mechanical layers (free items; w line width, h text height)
Top Overlay:
  drawing of 8 lines, arcs and shapes, not listed
  text "e" at 2978.59,3567.74 h405.77
  text "IMECAS" at 3530,3410 h48.19
Bottom Overlay:
  text "Ver.lpb20240311" at 4065,3929.99 h60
